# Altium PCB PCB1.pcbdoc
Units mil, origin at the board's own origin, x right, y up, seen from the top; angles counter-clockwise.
Board outline 3683.94 x 2210 mil, 2 copper layers (Top Layer, Bottom Layer); 36 components, 20 nets, 106 pads, 33 vias.
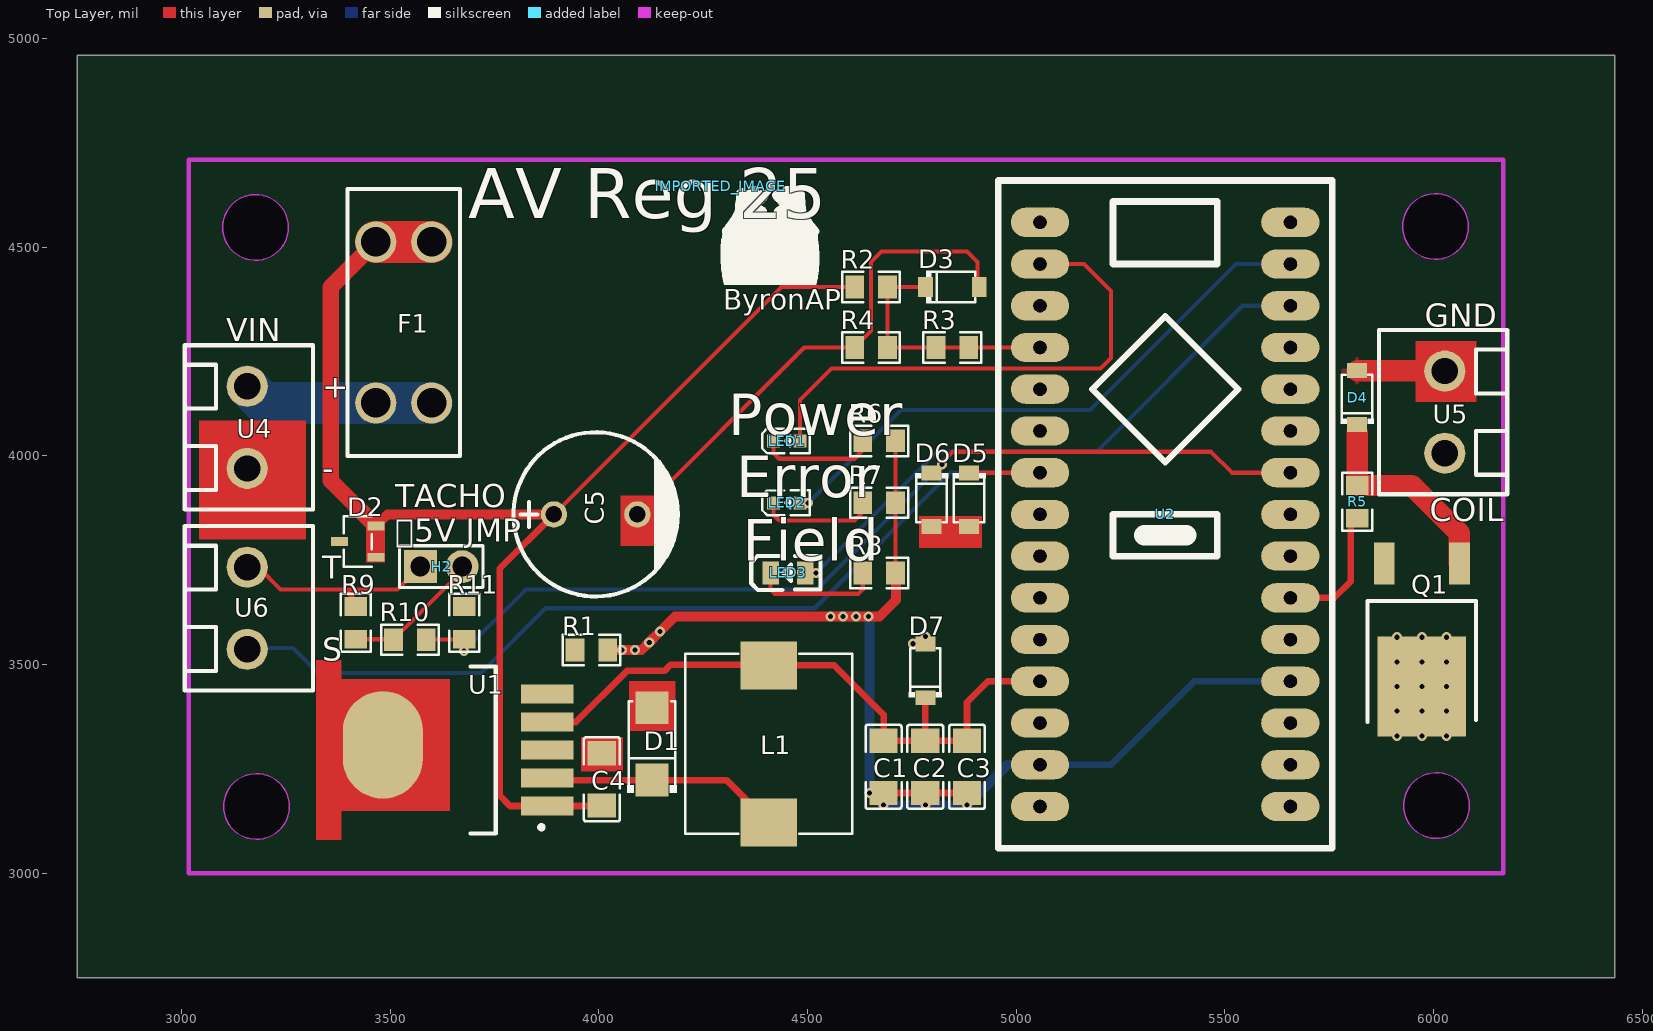
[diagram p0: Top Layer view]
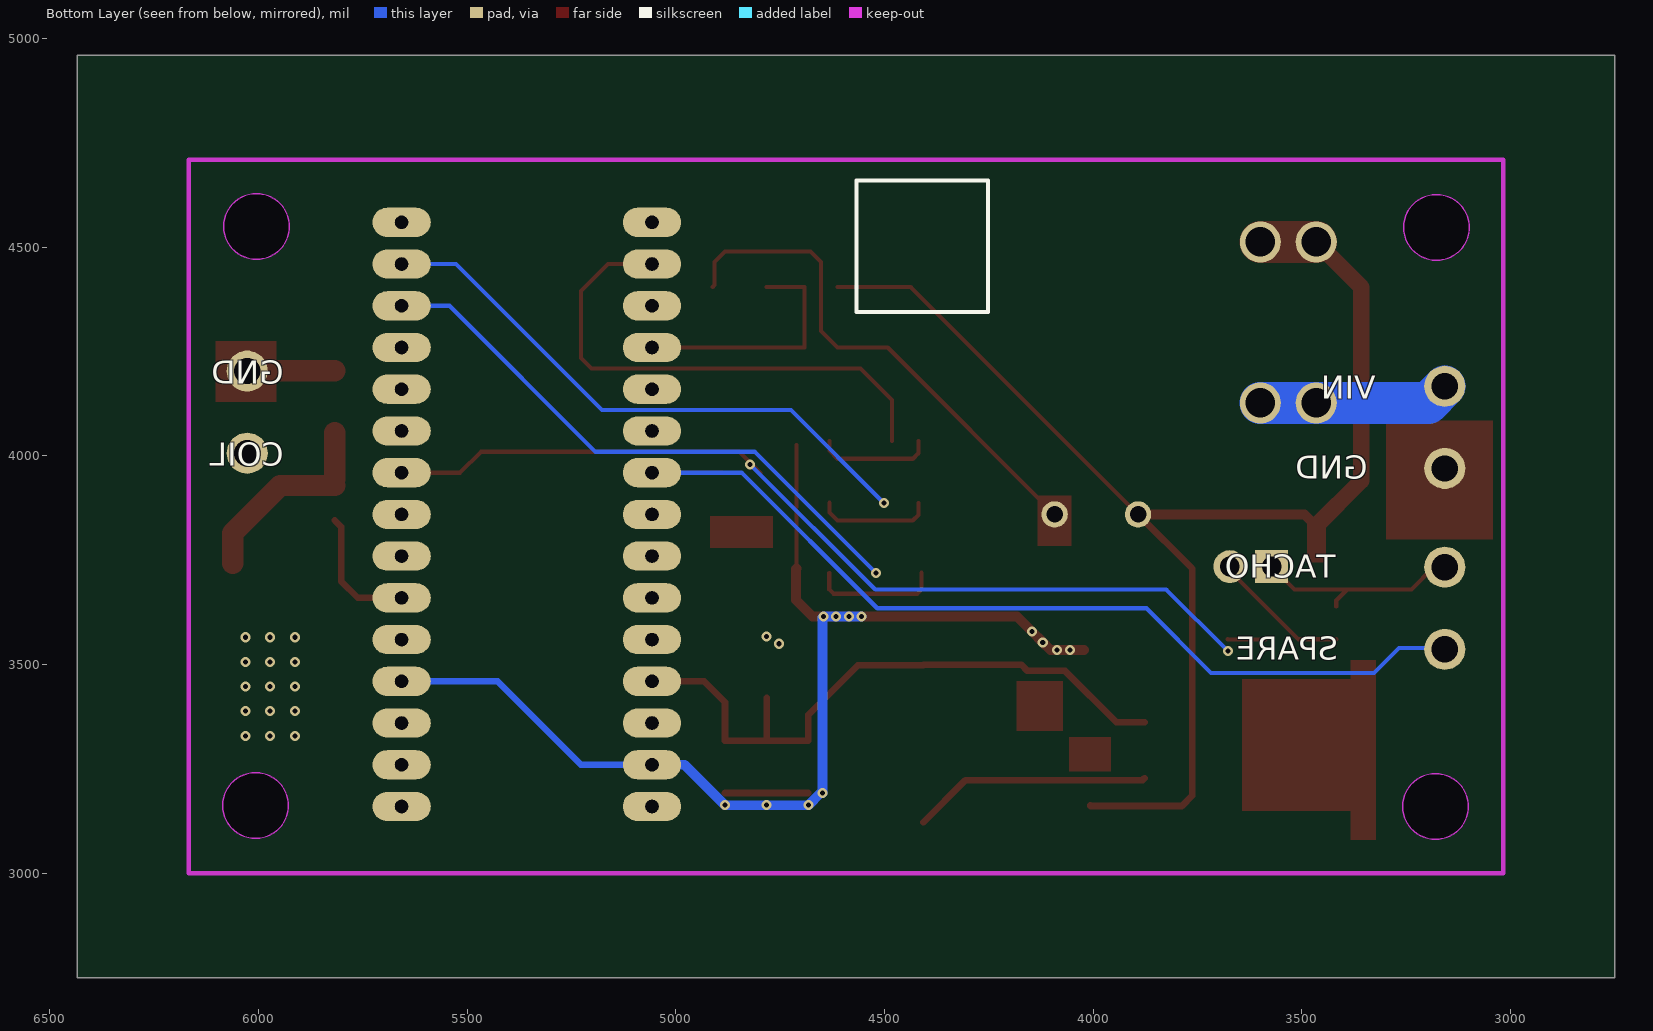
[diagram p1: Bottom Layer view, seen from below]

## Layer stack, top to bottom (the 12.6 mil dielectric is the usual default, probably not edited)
Top Layer: signal copper (thickness not stored)
Dielectric: dielectric 12.6, FR-4, Dk 4.8
Bottom Layer: signal copper (thickness not stored)

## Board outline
6433.94,2750 2750,2750 2750,4960 6433.94,4960
cut-out: 3255.71,4547.72 cw(c3176.97,4547.72) 3098.23,4547.72 cw(c3176.97,4547.72)
cut-out: 6083.43,4550 cw(c6004.69,4550) 5925.95,4550 cw(c6004.69,4550)
cut-out: 3257.99,3160 cw(c3179.25,3160) 3100.51,3160 cw(c3179.25,3160)
cut-out: 6085.71,3162.28 cw(c6006.97,3162.28) 5928.23,3162.28 cw(c6006.97,3162.28)

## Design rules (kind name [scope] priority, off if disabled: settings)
BoardOutlineClearance copperThickness1oz [All] p0: genericclearance=10 ignorepadtopadclearanceinfootprint=FALSE except(0: Arc-SplitContinuation Track-SplitContinuation SMDPad-SplitContinuation THPad-SplitContinuation Via-SplitContinuation Fill-SplitContinuation Poly-SplitContinuation Region-SplitContinuation Text-SplitContinuation; 6: Track-CutoutEdge SMDPad-CutoutEdge THPad-CutoutEdge Via-CutoutEdge Region-CutoutEdge; 11.8: Track-OutlineEdge SMDPad-OutlineEdge THPad-OutlineEdge Via-OutlineEdge Fill-OutlineEdge Region-OutlineEdge Poly-OutlineEdge Text-OutlineEdge Fill-CutoutEdge)
BoardOutlineClearance copperThickness2oz [All] p0: genericclearance=10 ignorepadtopadclearanceinfootprint=FALSE except(0: Arc-SplitContinuation Track-SplitContinuation SMDPad-SplitContinuation THPad-SplitContinuation Via-SplitContinuation Fill-SplitContinuation Poly-SplitContinuation Region-SplitContinuation Text-SplitContinuation; 6: Track-CutoutEdge SMDPad-CutoutEdge THPad-CutoutEdge Via-CutoutEdge Region-CutoutEdge; 11.8: Track-OutlineEdge SMDPad-OutlineEdge THPad-OutlineEdge Via-OutlineEdge Fill-OutlineEdge Region-OutlineEdge Poly-OutlineEdge Text-OutlineEdge Fill-CutoutEdge)
Clearance copperThickness1oz [(InNet('GND') OR InNet('FIELD-DRV') OR InNet('V-SENSE') OR InNet('ERROR-LED') OR InNet('FIELD-LED') OR InNet('PWR-LED') OR InNet('+5V') OR InNet('PGND') OR InNet('VIN') OR InNet('$1N1383') OR InNet('$1N2162') OR InNet('$1N3280') OR InNet('$1N3447') OR InNet('$1N3617') OR InNet('COIL') OR InNet('+12VIN') OR InNet('TACHO') OR InNet('SPARE-IN') OR InNet('TACHO-IN') OR InNet('$1N5056'))] p1: gap=7 ignorepadtopadclearanceinfootprint=FALSE except(4: Track-Track; 6: Track-SMDPad SMDPad-SMDPad Track-THPad SMDPad-THPad THPad-THPad Track-Via SMDPad-Via THPad-Via Via-Via SMDPad-Fill THPad-Fill Via-Fill Fill-Fill Track-Region SMDPad-Region THPad-Region Via-Region Region-Region Track-Poly SMDPad-Poly THPad-Poly Via-Poly Fill-Poly Region-Poly Poly-Poly Track-Text SMDPad-Text THPad-Text Via-Text Fill-Text Region-Text Poly-Text Text-Text; 6.9: Track-Hole SMDPad-Hole THPad-Hole Via-Hole Fill-Hole Region-Hole Poly-Hole Text-Hole Sheet-Hole; 11.8: Track-Fill Fill-Region Track-Sheet SMDPad-Sheet THPad-Sheet Via-Sheet Fill-Sheet Region-Sheet Poly-Sheet Text-Sheet)
Clearance copperThickness2oz [All] p1: gap=7 ignorepadtopadclearanceinfootprint=FALSE except(6: Track-SMDPad SMDPad-SMDPad Track-THPad SMDPad-THPad THPad-THPad Track-Via SMDPad-Via THPad-Via Via-Via SMDPad-Fill THPad-Fill Via-Fill Fill-Fill Track-Region SMDPad-Region THPad-Region Via-Region Region-Region Track-Poly SMDPad-Poly THPad-Poly Via-Poly Fill-Poly Region-Poly Poly-Poly Track-Text SMDPad-Text THPad-Text Via-Text Fill-Text Region-Text Poly-Text Text-Text; 6.9: Track-Hole SMDPad-Hole THPad-Hole Via-Hole Fill-Hole Region-Hole Poly-Hole Text-Hole Sheet-Hole; 8: Track-Track; 11.8: Track-Fill Fill-Region Track-Sheet SMDPad-Sheet THPad-Sheet Via-Sheet Fill-Sheet Region-Sheet Poly-Sheet Text-Sheet)
DiffPairsRouting differentialPair [All] p1: maxuncoupledlength=10 minlimit=5.9843 maxlimit=5.9843 mostfreqgap=5.9843 toplayer_minwidth=5 toplayer_prefwidth=10 toplayer_maxwidth=100 bottomlayer_minwidth=5 bottomlayer_prefwidth=10 bottomlayer_maxwidth=100
PasteMaskExpansion pasteMaskExpansion [All] p1: expansion=0
PlaneConnect innerPlane [All] p1: planeconnectstyle=Direct reliefexpansion=20 reliefentries=4 reliefconductorwidth=10 reliefairgap=10
PolygonConnect copperRegion [All] p1: connectstyle=Direct reliefentries=4 reliefconductorwidth=10 polygonreliefangle="90 Angle" airgapwidth=10
RoutingVias viaSize [All] p1: viastyle="Through Hole" holewidth=12.0078 minholewidth=11.811 maxholewidth=248.0314 width=24.0158 minwidth=19.685 maxwidth=393.7008
SolderMaskExpansion solderMaskExpansion [All] p1: useseparateexpansions=TRUE expansion=2.0079 expansionbottom=2.0079
Width copperThickness1oz [All] p1: maxlimit=100 minlimit=5 preferedwidth=10
Width copperThickness2oz [All] p1: maxlimit=100 minlimit=8 preferedwidth=10

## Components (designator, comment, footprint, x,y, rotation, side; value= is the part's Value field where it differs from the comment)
C1 "" C1206 4681.97,3255 r270 top
C2 "" C1206 4781.97,3255 r270 top
C3 "" C1206 4881.97,3255 r270 top
C4 "" C1206 4006.97,3225 r90 top
C5 "" CAP-TH_BD10.0-P5.00-D1.0-FD 3991.97,3860 r0 top
D1 "" SMA_L4.3-W2.6-LS5.2-RD 4126.97,3310 r90 top
D2 "" SOT-23-3_L3.0-W1.7-P0.95-LS2.9-BR 3421.97,3795 r0 top
D3 "" SOD-123_L2.7-W1.6-LS3.7-RD 4846.97,4405 r0 top
D4 "" SOD-123_L2.7-W1.6-LS3.7-RD 5816.97,4140 r90 top
D5 "" SOD-123_L2.7-W1.6-LS3.7-RD 4886.97,3895 r270 top
D6 "" SOD-123_L2.7-W1.6-LS3.7-RD 4796.97,3895 r270 top
D7 "" SOD-123_L2.7-W1.6-LS3.7-RD 4781.97,3485 r90 top
F1 "" FUSE-TH_4P-L16.0-W6.7 3531.97,4320 r90 top
H2 "" HDR-TH_2P-P2.54-V-M 3621.97,3735 r0 top
IMPORTED_IMAGE "IMPORTED_IMAGE" IMPORTED_IMAGE 4291.34,4646.82 r0 top
L1 "" IND-SMD_L10.8-W10.0_SLO1040H 4406.97,3310 r270 top
LED1 "" LED0603-RD 4449.94,4035.84 r0 top
LED2 "" LED0603-RD 4449.94,3887.54 r0 top
LED3 "" LED0805-R-RD 4452.54,3720 r0 top
Q1 "" TO-252-3_L6.5-W5.8-P4.58-BL 5971.97,3595 r180 top
R1 "" R0805 3981.97,3535 r180 top
R2 "" R0805 4651.97,4405 r0 top
R3 "" R0805 4846.97,4260 r0 top
R4 "" R0805 4651.97,4260 r0 top
R5 "" R0805 5816.97,3890 r90 top
R6 "" R0805 4671.25,4036.06 r0 top
R7 "" R0805 4671.25,3887.75 r0 top
R8 "" R0805 4671.25,3719.45 r0 top
R9 "" R0805 3416.97,3600 r270 top
R10 "" R0805 3546.97,3560 r0 top
R11 "" R0805 3676.97,3600 r270 top
U1 "" TO-263-5_L10.2-W8.9-P1.70-TL 3679.16,3295.15 r180 top
U2 "" NANO 5456.97,3510 r0 top
U4 "" CONN-TH_2P-P5.00_L7.8-W10.0 3156.97,4068.66 r270 top
U5 "" CONN-TH_2P-P5.00_L7.8-W10.0 6026.97,4105 r90 top
U6 "" CONN-TH_2P-P5.00_L7.8-W10.0 3156.97,3635 r270 top

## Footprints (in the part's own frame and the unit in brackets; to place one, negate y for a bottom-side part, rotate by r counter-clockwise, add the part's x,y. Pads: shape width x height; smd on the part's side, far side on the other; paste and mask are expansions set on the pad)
C1206 [mm]
  rect 1.485x1.728 smd: 1(-1.593,0) 2(1.593,0)
  silkscreen extent -2.56,-1.09 2.56,1.09
CAP-TH_BD10.0-P5.00-D1.0-FD [mm]
  round 1.6 hole 1: 1(-2.54,0) 2(2.54,0)
  silkscreen extent -5,-5 5.08,5
CONN-TH_2P-P5.00_L7.8-W10.0 [mm]
  round 2.5 hole 1.6: 1(-2.5,0) 2(2.5,0)
  silkscreen extent -5,-3.8 5,4
FUSE-TH_4P-L16.0-W6.7 [mm]
  round 2.5 hole 1.8: 1(-4.9,1.7) 2(4.9,1.7) 3(4.9,-1.7) 4(-4.9,-1.7)
  silkscreen extent -8.13,-3.43 8.13,3.43
HDR-TH_2P-P2.54-V-M [mm]
  rect 2x2 hole 1.2: 1(-1.27,0)
  round 2 hole 1.2: 2(1.27,0)
  silkscreen extent -2.54,-1.27 2.54,1.27
IMPORTED_IMAGE [mil]
  silkscreen extent 0,-236 236,0
IND-SMD_L10.8-W10.0_SLO1040H [mm]
  rect 2.924x3.42 smd: 1(4.778,0) 2(-4.778,0)
  silkscreen extent -5.48,-5.08 5.48,5.08
LED0603-RD [mm]
  rect 0.8x0.8 smd: 1(-0.799,0) 2(0.799,0)
  silkscreen extent -1.49,-0.75 1.39,0.76
LED0805-R-RD [mm]
  rect 1x1.4 smd: 1(1.05,0) 2(-1.05,0)
  silkscreen extent -2.22,-1.04 1.99,1.01
NANO [mil]
  oval 140x70 hole 31.5 slot 31.7 at 0 deg: 3.3V(-400,949.99) 5V(-400,-50) A0(-400,749.99) A1(-400,649.99) A2(-400,549.99) A3(-400,449.99) A4(-400,350) A5(-400,250) A6(-400,150) A7(-400,50) AREF(-400,849.99) D2(200,50) D3(200,150) D4(200,250) D5(200,350) D6(200,449.99) D7(200,549.99) D8(200,649.99) D9(200,749.99) D10(200,849.99) D11(200,949.99) D12(200,1049.99) D13(-400,1049.99) GND(-400,-250) GND1(200,-50) RAW(-400,-350) RST(-400,-150) RST1(200,-150) RX1(200,-250) TX0(200,-350)
  silkscreen extent -500,-450 300,1150
R0805 [mm]
  rect 1.133x1.377 smd: 1(-1,0) 2(1,0)
  silkscreen extent -1.76,-0.92 1.76,0.92
SMA_L4.3-W2.6-LS5.2-RD [mm]
  rect 2x2 smd: 1(-2.2,0) 2(2.2,0)
  silkscreen extent -2.98,-1.5 2.6,1.5
SOD-123_L2.7-W1.6-LS3.7-RD [mm]
  rect 0.91x1.22 smd: 1(-1.635,0) 2(1.635,0)
  silkscreen extent -1.6,-1 1.38,1
SOT-23-3_L3.0-W1.7-P0.95-LS2.9-BR [mil]
  rect 40.85x20.95 smd: 1(43.36,-37.4) 2(43.36,37.4) 3(-43.36,0)
  silkscreen extent -34,-60 34,60
TO-252-3_L6.5-W5.8-P4.58-BL [mm]
  rect 1.27x2.54 smd: 1(-2.288,-3.747) 3(2.288,-3.745)
  rect 5.4x6.1 smd: 2(-0.002,3.747)
  silkscreen extent -3.31,-1.46 3.3,5.9
TO-263-5_L10.2-W8.9-P1.70-TL [mm]
  rect 3.2x1.15 smd: 1(-5.008,3.404) 2(-5.008,1.702) 3(-5.008,0) 4(-5.008,-1.702) 5(-5.008,-3.404)
  oval 4.877x6.553 smd: 6(5.008,-0.317)
  Top Layer region: 0.944,3.683 7.548,3.683 7.548,5.461 9.072,5.461 9.072,-5.461 7.548,-5.461 7.548,-4.317 0.944,-4.317
  silkscreen extent -4.77,-5.08 -0.33,5.08

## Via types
v1: diameter 24.02, hole 12.01, Top Layer to Bottom Layer, 33 vias

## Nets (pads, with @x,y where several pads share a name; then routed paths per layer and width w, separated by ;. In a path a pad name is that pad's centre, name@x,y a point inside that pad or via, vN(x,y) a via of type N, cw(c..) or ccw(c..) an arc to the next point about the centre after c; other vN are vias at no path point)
$1N1383: D1.1 L1.1 U1.2 | length 574.7
  Top Layer w15.75: U1.2 3881.08,3223.39 D1.1 4305.47,3223.39 L1.1
$1N2162: D4.1 Q1.1 R5.2 | length 476.1
  Top Layer w51.18: R5.2 5947.58,3929.37 6062.05,3814.9 Q1.1 ; R5.2@5816.97,3944.37 5816.97,4055.63
$1N3280: LED1.1 R6.1 | length 279.1
  Top Layer w10: LED1.1@4418.45,4035.71 4418.45,4006.67 4431.95,3993.17 4611.95,3993.17 4631.86,4013.08 R6.1@4631.86,4035.92
$1N3447: LED2.1 R7.1 | length 279.1
  Top Layer w10: LED2.1 4418.47,3858.5 4431.97,3845 4611.97,3845 4631.88,3864.91 R7.1
$1N3617: LED3.2 R8.1 | length 308.5
  Top Layer w10: LED3.2 4411.19,3680 4421.19,3670 4621.97,3670 4631.97,3680 4631.97,3719.36 R8.1
$1N5056: H2.2 R9.2 R10.1 | length 334
  Top Layer w10: R9.2 3506.97,3560.63 R10.1 3671.97,3724.37 H2.2
+5V: C1.1 C2.1 C3.1 D7.1 L1.2 U1.4 U2.5V | length 1565.7
  Top Layer w15.75: U1.4 3944.12,3362.15 4066.97,3485 4156.97,3485 4171.97,3500 4405.08,3500 L1.2 4563.86,3498.11 4681.97,3380 C1.1 C2.1 ; D7.1 C2.1 ; U2.5V 4931.97,3460 4881.97,3410 C3.1 C2.1
+12VIN: F1.1 F1.4 U4.1 | length 458.5
  Bottom Layer w100: U4.1 3196.97,4127.09 F1.1 F1.4
COIL: Q1.2 U5.1
  other v1: 5913,3329.37 5972.05,3329.37 6031.11,3329.37 5913,3388.42 5972.05,3388.42 6031.11,3388.42 5913,3447.48 5972.05,3447.48 6031.11,3447.48 5913,3506.53 5972.05,3506.53 6031.11,3506.53 5913,3565.59 5972.05,3565.59 6031.11,3565.59
ERROR-LED: LED2.2 U2.D11 | length 1392.7
  Bottom Layer w10: v1(4501.42,3887.55) 4723.87,4110 5176.97,4110 5526.96,4459.99 U2.D11
FIELD-DRV: R5.1 U2.D3 | length 313.4
  Top Layer w15.75: U2.D3 5761.97,3660 5801.97,3700 5801.97,3830.63 R5.1@5816.97,3845.63
FIELD-LED: LED3.1 U2.D10 | length 1402.4
  Bottom Layer w10: v1(4519.93,3719.45) 4810.48,4010 5191.97,4010 5541.96,4359.99 U2.D10
GND: C1.2 C2.2 C3.2 D7.2 R1.1 R6.2 R7.2 R8.2 U2.GND U2.GND1 | length 2960.7
  Top Layer w10: R8.2@4710.62,3730.2 R7.2@4710.62,3867.75 ; R7.2@4710.62,3877.75 R6.2@4710.62,4026.06
  Top Layer w15.75: C1.2 C2.2 C3.2
  Top Layer w23.62: R1.1 v1(4055.04,3535) v1(4086.78,3535) 4101.97,3535 v1(4120.45,3553.48) v1(4146.24,3579.27) 4181.97,3615 v1(4554.85,3615) 4585.6,3615 4616.3,3615 v1(4646.01,3615) 4671.97,3615 4711.97,3655 4711.97,3728.85 R8.2@4710.62,3730.2
  Bottom Layer w15.75: U2.GND 5226.97,3260 5426.97,3460 U2.GND1
  Bottom Layer w23.62: v1(4554.85,3615) v1(4646.01,3615) 4647.95,3613.06 v1(4647.95,3192.3) 4652.74,3192.3 v1(4681.97,3163.07) v1(4781.97,3163.07) v1(4881.97,3163.07) 4978.9,3260 U2.GND
  other v1: 4751.97,3550 4781.97,3566.83 4585.24,3615 4615.63,3615
PGND: C4.2 C5.2 D1.2 D2.3 D3.2 D4.2 D5.2 D6.2 Q1.3 R1.2 R4.1 R11.1 U1.3 U1.5 U1.6 U4.2 U5.2 | length 1455.5
  Top Layer w10: C5.2 4491.97,4260 R4.1 4651.97,4299.37 4651.97,4465 4676.97,4490 4881.97,4490 4906.97,4465 4906.97,4409.37 D3.2
  Top Layer w51.18: D4.2 6026.02,4204.37 U5.2
PWR-LED: LED1.2 U2.3.3V | length 1242.7
  Top Layer w10: LED1.2 4481.42,4134.45 4556.97,4210 5201.97,4210 5226.97,4235 5226.97,4395 5161.98,4459.99 U2.3.3V
SPARE-IN: D5.1 U2.A3 U6.2 | length 2300.6
  Top Layer w10: U2.A3 D5.1@4891.96,3959.99 ; D5.1@4891.96,3959.99 4891.35,3959.37 D5.1 4887.59,3959.99 D5.1@4891.96,3959.99
  Bottom Layer w10: U6.2 3160.4,3540 3266.97,3540 3326.97,3480 3716.97,3480 3871.97,3635 4516.97,3635 4841.96,3959.99 U2.A3
TACHO: D6.1 R10.2 R11.2 U2.D6 | length 2323
  Top Layer w10: R10.2 3676.34,3560 R11.2 ; D6.1 4847.6,4010 5466.97,4010 5516.97,3960 U2.D6
  Bottom Layer w10: v1(3676.97,3532.35) 3824.63,3680 4521.97,3680 v1(4821.97,3980)
TACHO-IN: H2.1 R9.1 U6.1 | length 518.5
  Top Layer w10: U6.1 3183.55,3733.43 3236.97,3680 3390.74,3680 ; R9.1 3416.97,3653.77 3390.74,3680 ; H2.1@3576.97,3740 3516.97,3680 3390.74,3680
V-SENSE: D3.1 R2.2 R3.1 R3.2 R4.2 U2.A0 | length 601.9
  Top Layer w10: D3.1 R2.2 R4.2 R3.1 R3.2 U2.A0
VIN: C4.1 C5.1 D2.1 D2.2 F1.2 F1.3 R2.1 U1.1 | length 3272
  Top Layer w10: C5.1 4436.97,4405 R2.1
  Top Layer w15.75: C5.1 3761.97,3730 3761.97,3186.15 3786.97,3161.15 U1.1 4005.82,3161.15 C4.1
  Top Layer w23.62: D2.2 3492.93,3860 C5.1
  Top Layer w39.37: F1.2 3356.97,4404.84 3356.97,3940.76 D2.2
  Top Layer w100: F1.2 F1.3
pads on no net: U2.A1 U2.A2 U2.A4 U2.A5 U2.A6 U2.A7 U2.AREF U2.D2 U2.D4 U2.D5 U2.D7 U2.D8 U2.D9 U2.D12 U2.D13 U2.RAW U2.RST U2.RST1 U2.RX1 U2.TX0

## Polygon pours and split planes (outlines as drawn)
PGND on Top Layer (solid, remove dead copper, pour order 0): 3041.97,3810 6126.97,3810 6126.97,3025 3041.97,3025
COIL on Bottom Layer (solid, remove dead copper, pour order 4): 5831.97,4104.26 6119.62,4104.26 6119.62,3290 5831.97,3290
PGND on Top Layer (solid, remove dead copper, pour order 2): 5756.97,4279.53 6121.97,4279.53 6121.97,3805 5756.97,3805
GND on Bottom Layer (solid, remove dead copper, pour order 6): 3036.97,4665 6131.97,4665 6131.97,3030 3036.97,3030

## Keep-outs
Board Outline Layer:
  circle w1: c3176.97,4547.72 r78.74
  region: 3255.71,4547.72 cw(c3176.97,4547.72) 3098.23,4547.72 cw(c3176.97,4547.72)
  circle w1: c6004.69,4550 r78.74
  region: 6083.43,4550 cw(c6004.69,4550) 5925.95,4550 cw(c6004.69,4550)
  circle w1: c3179.25,3160 r78.74
  region: 3257.99,3160 cw(c3179.25,3160) 3100.51,3160 cw(c3179.25,3160)
  circle w1: c6006.97,3162.28 r78.74
  region: 6085.71,3162.28 cw(c6006.97,3162.28) 5928.23,3162.28 cw(c6006.97,3162.28)
  lines w10: 3016.97,3000 6166.97,3000 6166.97,4710 3016.97,4710 3016.97,3000

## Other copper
Top Layer:
  region net VIN: 3441.97,3845 3486.97,3845 3486.97,3745 3441.97,3745
  region net PGND: 3956.97,3325.93 4056.97,3325.93 4056.97,3245 3956.97,3245
  region net PGND: 4071.97,3460 4183.12,3460 4183.12,3341.47 4071.97,3341.47
  region net PGND: 4051.97,3905 4131.97,3905 4131.97,3785 4051.97,3785
  region net PGND: 5956.97,4275 6101.97,4275 6101.97,4129.72 5956.97,4129.72
  region net PGND: 4766.97,3855 4916.97,3855 4916.97,3780 4766.97,3780
  region net PGND: 3041.97,4085 3296.97,4085 3296.97,3800 3041.97,3800

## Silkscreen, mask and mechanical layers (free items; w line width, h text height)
Top Silkscreen Layer:
  text "AV Reg 25" at 3686.97,4570 h120
  text "ByronAP" at 4297.98,4350 h49.21
  text "GND" at 5979.47,4310.27 h55.12
  text "VIN" at 3106.97,4275 h55.12
  text "+" at 3336.97,4139.54 h55.12
  text "Power" at 4309.84,4050 h100
  text "-" at 3336.97,3942.69 h55.12
  text "Error" at 4328.49,3901.7 h100
  text "COIL" at 5991.37,3843.55 h55.12
  text "TACHO /  5V JMP" at 3511.97,3795 h55.12
  text "Field" at 4344.34,3748.35 h100
  text "T" at 3336.97,3705.88 h55.12
  text "S" at 3336.97,3509.03 h55.12
Bottom Silkscreen Layer:
  lines w10: 4251.97,4345.04 4566.93,4345.04 4566.93,4660 4251.97,4660 4251.97,4345.04
  text "GND" at 5939.77,4172.61 h55.12
  text "VIN" at 3321.97,4137.34 h55.12
  text "COIL" at 5939.77,3976.82 h55.12
  text "GND" at 3341.07,3944.87 h55.12
  text "TACHO" at 3418.27,3708.06 h55.12
  text "SPARE" at 3412.37,3511.21 h55.12
Bottom Solder Mask Layer:
  region: 5831.97,3645 6116.97,3645 6116.97,3290 5831.97,3290
Mechanical Layer:
  circle w1: c3176.97,4547.72 r78.74
  circle w1: c6004.69,4550 r78.74
  circle w1: c3179.25,3160 r78.74
  circle w1: c6006.97,3162.28 r78.74
Mech6:
  lines w10: 3755.8,3860 3755.8,4608.03 4228.24,4608.03 4228.24,3860 3755.8,3860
